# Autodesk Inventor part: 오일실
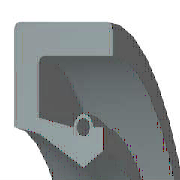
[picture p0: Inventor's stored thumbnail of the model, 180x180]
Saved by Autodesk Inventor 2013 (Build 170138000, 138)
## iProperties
IsCustomPart: 0
Company: 한국ATC센터
Created: 2014-08
Part Number: 오일실
Material: 고무
Description: 오일-실
Document SubType Name: Modeling
Standard: KS B 2804
Designer: KYOUNG IL JANG
Standards Organization: KS
Language: ko-KR
Size Designation: S - 17 30 8
Categories: <MemberInstance><Categories><Category DisplayName="샤프트 부품" InternalName="7f7aeb1f-a693-4053-b835-cee3144e0d98" Mnemonic="SHFT"><Category DisplayName="실링" Intern
Density: 0.93 g/cm^3
Mass: 1.6913 g
Surface Area: 28.0102 cm^2
Volume: 1.81861 cm^3
Author: KYOUNG IL JANG
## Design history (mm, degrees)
revolve "본체" stored, may be unused: angle "d17" = 90 deg
revolve "스프링1" stored, may be unused: angle "d18" = 90 deg
body "Solid1"
sketch "스케치1"
  geometry: L1 (0, 15)-(8, 15); L2 (8, 15)-(8, 13.75); L3 (8, 13.75)-(1.75, 13.75); L4 (0, 15)-(0, 10.6); L5 (0, 10.6)-(1.75, 10.25); L6 (1.75, 10.25)-(4.9, 8.5); L7 (4.9, 8.5)-(0, 8.5); L8 (6.3, 9.375)-(6.3, 10.6); L9 (0, 0)-(9.586, 0) reference; L10 (4.9, 8.5)-(6.3, 9.375); L11 (0, 18)-(0, -3) reference; L12 (-1.917, 0)-(11.503, 0) reference; L13 (4.2, 10.6)-(1.75, 11.09); L14 (1.75, 11.09)-(1.75, 13.75); L15 (6.3, 10.6)-(5.6, 10.6); C1 r 0.455 at (4.9, 10.6); A1 r 0.7 centre (4.9, 10.6) between (5.6, 10.6) and (4.2, 10.6)
  constraints: 26 end point, 5 horizontal alignment, 4 perpendicular, 2 centre point, 2 collinear, 2 horizontal, 2 parallel, 2 point on circle, 2 point on line, 2 vertical alignment, 1 coincident
  dimensions: "d0" = 30 diameter of L1 L9 (= SD2); "d1" = 18.75 diameter of L8.start L9 (= ABDM); "d2" = 1.25 distance of L1.end L2.end (computed from SD); "d3" = 0.91 diameter of C1 (= SPDI); "d4" = 1.4 diameter of A1 (= SPDA); "d5" = 17 diameter of L6.end L9 (= NND); "d6" = 20.5 diameter of L5.end L9 (= TKDM); "d7" = 21.2 diameter of L4.end L9 (= HLDM); "d8" = 4.9 distance from line of C1.centre L4 (= SPDST); "d9" = 6.3 distance between parallel lines of L8 L4 (= SDI); "d10" = 8 distance between parallel lines of L2 L4 (= SWDT); "d12" = 1.75 distance between parallel lines of L14 L4 (= SD)
fillet "모깎기1" dims "d11" = 0.3 (= RR)
other parameters: "SD2" = 30 [user parameter; used in 1 equation term], "SWDT" = 8 [user parameter; used in 1 equation term], "RR" = 0.3 [user parameter; used in 1 equation term], "SD" = 1.75 [user parameter; used in 2 equation terms], "NND" = 17 [user parameter; used in 1 equation term], "SPDA" = 1.4 [user parameter; used in 1 equation term], "SPDI" = 0.91 [user parameter; used in 1 equation term], "TKDM" = 20.5 [user parameter; used in 1 equation term], "HLDM" = 21.2 [user parameter; used in 1 equation term], "ABDM" = 18.75 [user parameter; used in 1 equation term], "SDI" = 6.3 [user parameter; used in 1 equation term], "SPDST" = 4.9 [user parameter; used in 1 equation term], "d13" = 0, "d14" = 0, "d15" = 0, "LAB" = 0.35 [user parameter]
